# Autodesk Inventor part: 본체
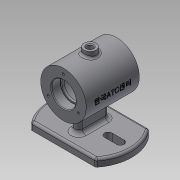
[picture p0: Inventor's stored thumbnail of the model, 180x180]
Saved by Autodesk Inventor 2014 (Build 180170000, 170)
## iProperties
Created: 2017-12
Part Number: 본체
Material: 일반
Document SubType Name: Modeling
Designer: 학생용
Density: 1 g/cm^3
Appearance: 기본값
Author: 학생용
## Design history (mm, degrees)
sketch "스케치1"
  geometry: L1 (0, 0)-(70, 0); L2 (70, 0)-(70, 30); L3 (70, 30)-(0, 30); L4 (0, 30)-(0, 0); L5 (0, 16)-(11.7, 16); L6 (12, 15.7)-(12, 14); L7 (12, 14)-(15, 14); L8 (15, 14)-(15, 22); L9 (18, 25)-(52, 25); L10 (55, 22)-(55, 14); L11 (55, 14)-(58, 14); L12 (58, 14)-(58, 15.7); L13 (58.3, 16)-(70, 16); A1 r 0.3 centre (11.7, 15.7) between (12, 15.7) and (11.7, 16); A2 r 0.3 centre (58.3, 15.7) between (58.3, 16) and (58, 15.7); A3 r 3 centre (18, 22) between (18, 25) and (15, 22); A4 r 3 centre (52, 22) between (55, 22) and (52, 25)
  constraints: 26 end point, 8 point on circle, 8 tangent, 7 parallel, 5 perpendicular, 4 centre point, 2 equal radius, 2 point on line, 1 horizontal
  dimensions: "d0" = 70 distance of L1.start L1.end; "d1" = 60 diameter of L3 L1; "d2" = 32 diameter of L13 L1; "d3" = 28 diameter of L11 L1; "d4" = 50 diameter of L9 L1; "d5" = 28 diameter of L7 L1; "d6" = 32 diameter of L5 L1; "d7" = 12 distance between parallel lines of L4 L6; "d8" = 40 distance between parallel lines of L10 L8; "d9" = 12 distance between parallel lines of L2 L12; "d10" = 3 distance between parallel lines of L6 L8; "d11" = 0.3 radius of A1; "d12" = 3 radius of A3
revolve "회전1" sketch "스케치1" stored, may be unused: angle "d13" = 90 deg
chamfer "모따기1" distance "d14" = 1; stored, may be unused: second distance "d15" = 2, angle "d16" = 45 deg
node "작업 평면1"
sketch "스케치2"
  geometry: C1 r 8 at (0, 35); 1 further point
  constraints: 1 centre point, 1 vertical alignment
  dimensions: "d18" = 35 distance of point (0, 0) C1.centre; "d19" = 16 diameter of C1
extrude "돌출1" join sketch "스케치2" stored distance "d20" = 35 (= d18); taper "d21" = 0 deg
sketch "스케치3"
  geometry: C1 r 8 at (0, 0) reference; C2 r 4 at (0, 0); 1 further point
  constraints: 1 centre point, 1 coincident
  dimensions: "d22" = 8 diameter of C2
extrude "돌출2" cut sketch "스케치3" stored distance "d23" = 10; taper "d24" = 0 deg
chamfer "모따기2" distance "d25" = 1; stored, may be unused: second distance "d26" = 2, angle "d27" = 45 deg
fillet "모깎기1" dims "d28" = 3
sketch "스케치4" dims "d29" = 46
  geometry: C1 r 30 at (0, 0) reference; C2 r 17 at (0, 0) reference; 2 further points
  constraints: 2 vertical alignment, 1 coincident, 2 other
hole "구멍1" sketch "스케치4" at (0, 23) diameter "d30" = 3.242; stored, may be unused: countersink angle "d34" = 90 deg, drill point angle "d36" = 118 deg; dims "d31" = 8, "d32" = 4, "d33" = 2, "d35" = 10
node "작업 평면2"
node "작업 평면3"
sketch "스케치5"
  geometry: L1 (-42.426, 70)-(42.426, 70); L2 (-42.426, 0)-(42.426, 0); C1 r 8 at (0, 35) reference; A1 r 55 centre (0, 35) between (-42.426, 70) and (-42.426, 0); A2 r 55 centre (0, 35) between (42.426, 0) and (42.426, 70); 1 further point
  constraints: 4 end point, 4 point on circle, 2 centre point, 1 coincident, 1 horizontal, 1 parallel
  dimensions: "d43" = 35 distance from line of L2 A1.centre; "d44" = 35 distance from line of L1 C1.centre; "d45" = 55 radius of A1; "d46" = 55 radius of A2
extrude "돌출3" join sketch "스케치5" distance "d47" = 10; taper "d48" = 0 deg
fillet "모깎기2" dims "d49" = 3
fillet "모깎기3" dims "d50" = 3
sketch "스케치6"
  geometry: L1 (40.988, 3)-(-40.988, 3) reference; L2 (0, 20)-(0, 50); L3 (5, 20)-(5, 50); L4 (-5, 50)-(-5, 20); A1 r 52 centre (0, 35) between (-40.988, 67) and (-40.988, 3) reference; A2 r 5 centre (0, 20) between (-5, 20) and (5, 20); A3 r 5 centre (0, 50) between (5, 50) and (-5, 50); 1 further point
  constraints: 8 end point, 4 point on circle, 4 tangent, 2 centre point, 1 midpoint, 1 parallel, 1 perpendicular
  dimensions: "d51" = 30 distance of L2.end L2.start; "d52" = 5 radius of A2
extrude "돌출4" join sketch "스케치6" stored distance "d53" = 10; taper "d54" = 0 deg
sketch "스케치7"
  geometry: L1 (-40.988, 67)-(40.988, 67) reference; L2 (40, 35)-(24, 35); L3 (40, 30)-(24, 30); L4 (24, 40)-(40, 40); L5 (-24, 35)-(-40, 35); L6 (-24, 30)-(-40, 30); L7 (-40, 40)-(-24, 40); A1 r 52 centre (0, 35) between (40.988, 3) and (40.988, 67) reference; A2 r 5 centre (40, 35) between (40, 30) and (40, 40); A3 r 5 centre (24, 35) between (24, 40) and (24, 30); A4 r 5 centre (-24, 35) between (-24, 30) and (-24, 40); A5 r 5 centre (-40, 35) between (-40, 40) and (-40, 30); 3 further points
  constraints: 16 end point, 8 point on circle, 8 tangent, 4 centre point, 4 parallel, 2 horizontal alignment, 2 midpoint
  dimensions: "d56" = 24 distance of L2.end A1.centre; "d57" = 16 distance of L2.start L2.end; "d58" = 5 radius of A2; "d59" = 24 distance of L5.start A1.centre; "d60" = 16 distance of L5.end L5.start; "d61" = 5 radius of A5
extrude "돌출5" cut sketch "스케치7" stored distance "d62" = 10; taper "d63" = 0 deg
node "작업 평면4"
sketch "스케치8"
  geometry: L1 (8.689, 8.94)-(61.311, 8.94); L2 (61.311, 8.94)-(61.311, -8.94); L3 (61.311, -8.94)-(8.689, -8.94); L4 (8.689, -8.94)-(8.689, 8.94); L5 (8.689, 0)-(61.311, 0); L6 (35, 8.94)-(35, -8.94); L7 (0, -30)-(0, 30) reference; 1 further point
  constraints: 4 end point, 4 midpoint, 2 other
  dimensions: "d65" = 35 distance between parallel lines of L6 L7; "d66" = 30 distance from line of L7.end L5
feature "엠보싱1" sketch "스케치8" dims "d67" = 0.5, "d68" = 0
fillet "모깎기5" dims "d69" = 5
node "솔리드1"
pattern_circular "원형 패턴1" dims angle "d38" = 360 deg
mirror "대칭1"
other parameters: "d17" = 37, "d40" = 35, "d41" = -62, "d64" = 30.5
